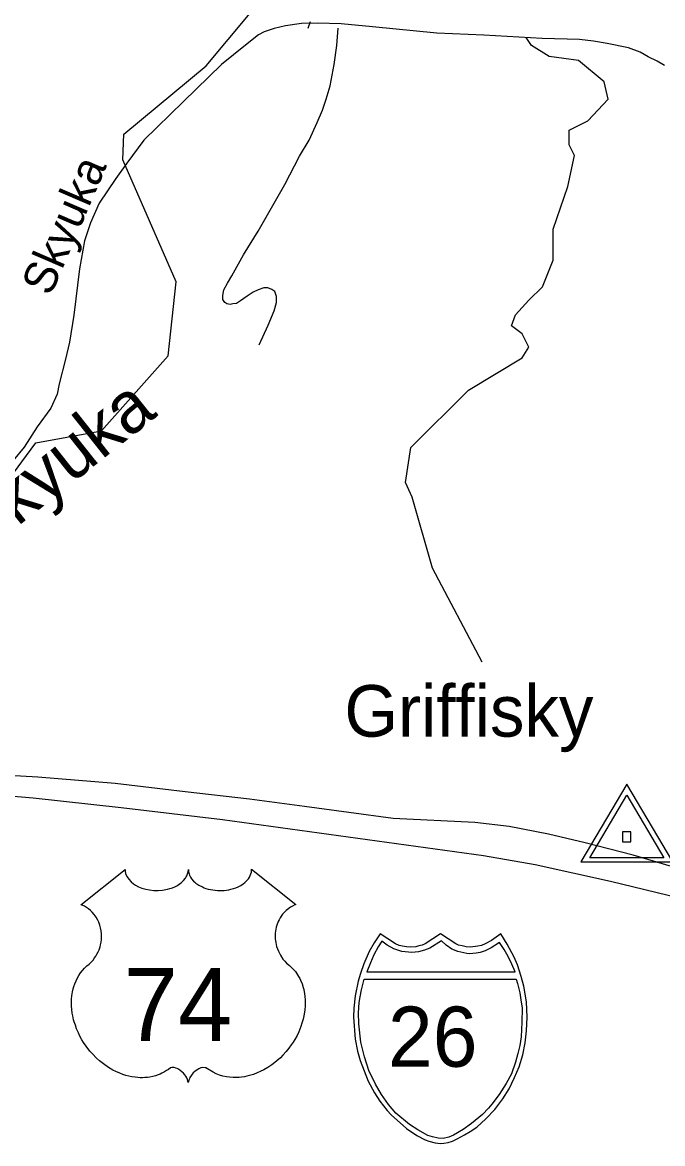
# Model space of a CAD drawing. Extents: x 990631 to 1056237, y 535999 to 585651.
# Drawn here: x 1037330 to 1039191, y 561980 to 565244 of the extents above; entities that cross this region are included whole.
import ezdxf

# ---------------------------------------------------------------- set-up
doc = ezdxf.new("R2010")
doc.units = 0
for name, color, linetype in [('Exist Hydrographic Creek Single Shore', 7, 'Continuous'), ('Exist Hydrographic Creek Single Shore Label', 7, 'Continuous'), ('Exist Road Non-System Type 51', 7, 'Continuous'), ('Exist Road Primary Interstate Divided Center Attributed', 7, 'Continuous'), ('Exist Road Primary Interstate Shield CELL', 7, 'Continuous'), ('Exist Road Primary Interstate Shield Number Label', 7, 'Continuous'), ('Exist Road Primary US Shield CELL', 7, 'Continuous'), ('Exist Road Primary US Shield Number Label', 7, 'Continuous'), ('Exist Road Secondary Type 51 Attributed', 7, 'Continuous'), ('Exist Road Secondary Type 51 Label', 7, 'Continuous'), ('Exist Survey Geodetic Marker CELL', 7, 'Continuous'), ('Exist Survey Geodetic Marker Label', 7, 'Continuous')]:
    doc.layers.add(name, color=color, linetype=linetype)

msp = doc.modelspace()

# ---------------------------------------------------------------- linework, layer by layer
at = {"layer": 'Exist Hydrographic Creek Single Shore'}
msp.add_lwpolyline([(1037044.6, 563559.5), (1037169.3, 563750.7), (1037368.1, 564019.8), (1037559.1, 564054.9), (1037753.3, 564272.7), (1037776.9, 564488.9), (1037621.7, 564843.2), (1037624, 564918.6), (1037863.8, 565117.3), (1038297.5, 565637), (1038320.6, 565836.7), (1038070.8, 566104.3), (1037992.3, 566256.9), (1037808.4, 567022), (1037738.6, 567180.9), (1037374.6, 567536.2), (1037272.5, 567731.9), (1037276.5, 567856.5), (1037246.9, 567972), (1036894.9, 568435.2)], dxfattribs=at)
at = {"layer": 'Exist Road Non-System Type 51'}
msp.add_line((1038166.4, 565245.3), (1038159.8, 565225.4), dxfattribs=at)
for points in [[(1038018.1, 564305.3), (1038044.1, 564362.6), (1038061.3, 564404.1), (1038068.2, 564428), (1038068.7, 564445.7), (1038063.2, 564460.1), (1038055.3, 564466.2), (1038043.4, 564470.7), (1038031.4, 564471.1), (1038015.3, 564465.6), (1038001, 564458.1), (1037982.7, 564446.7), (1037964.2, 564433.2), (1037951.9, 564425.5), (1037941.9, 564423.9), (1037933.8, 564422.3), (1037923.9, 564424.5), (1037917.9, 564428.6), (1037912.3, 564436.9), (1037912.7, 564448.9), (1037915.3, 564464.8), (1037925.9, 564484.4), (1037938.5, 564506), (1037972.5, 564566.9), (1038014.7, 564635.7), (1038057.3, 564710.5), (1038093.1, 564771.4), (1038135.8, 564854), (1038163.3, 564901.2), (1038187, 564952.4), (1038202.1, 564987.9), (1038213.1, 565019.7), (1038224.5, 565059.3), (1038236.4, 565121), (1038244.3, 565176.7), (1038247.9, 565226.6)], [(1038666.2, 563381.7), (1038522, 563654.7), (1038463.5, 563861.4), (1038444, 563904.3), (1038459.6, 564005.7), (1038627.2, 564173.5), (1038783.2, 564267.1), (1038802.7, 564298.3), (1038783.2, 564337.3), (1038752, 564360.7), (1038763.7, 564391.9), (1038802.7, 564434.8), (1038841.6, 564473.8), (1038872.8, 564551.8), (1038872.8, 564641.5), (1038915.7, 564766.3), (1038935.2, 564856), (1038919.6, 564887.2), (1038919.6, 564930.1), (1038974.2, 564957.4), (1039032.6, 565019.9), (1039021, 565070.6), (1038946.9, 565133), (1038861.1, 565144.7), (1038810.4, 565175.9), (1038810.4, 565175.9), (1038794.9, 565199.3)]]:
    msp.add_lwpolyline(points, dxfattribs=at)
at = {"layer": 'Exist Road Primary Interstate Divided Center Attributed'}
for points in [[(1039600.5, 562674), (1039581.5, 562681.8), (1039260.3, 562773.6), (1039105.6, 562819.5), (1038966.3, 562855.2), (1038859.2, 562880.8), (1038745.4, 562902.9), (1038645.1, 562914.8), (1038408, 562926.1), (1038149.5, 562961), (1037990.1, 562982.4), (1037802.6, 563003.9), (1037599, 563028), (1037373.9, 563046.7), (1037155.6, 563058.8), (1036983.1, 563069), (1036964, 563070.2), (1036848.9, 563077.1), (1036652.4, 563089.6)], [(1036616.9, 563035.1), (1037143.5, 563005.2), (1037360.5, 562986.4), (1037616.4, 562958.3), (1037911.1, 562923.5), (1038670.6, 562818.9), (1038820.6, 562792.1), (1039040.2, 562743.9), (1039239.7, 562694.9)]]:
    msp.add_lwpolyline(points, dxfattribs=at)
at = {"layer": 'Exist Road Primary Interstate Shield CELL'}
for points in [[(1038545.6, 561980), (1038555.1, 561980.9), (1038567.8, 561983.3), (1038580.2, 561987.4), (1038594.3, 561993.7), (1038615.2, 562005.2), (1038631.9, 562015), (1038651.3, 562028), (1038677.4, 562051.7), (1038703.4, 562079.1), (1038726.4, 562110.2), (1038744.7, 562139.2), (1038760.7, 562172.3), (1038774.2, 562203.3), (1038784.9, 562238.6), (1038791.9, 562272.8), (1038795.5, 562308.5), (1038797.9, 562348.1), (1038795.2, 562392.6), (1038787.4, 562438.2), (1038780.2, 562466.5), (1038769.1, 562500.5), (1038760.1, 562522.2), (1038739.3, 562560.6), (1038720.5, 562590.2), (1038693.3, 562571), (1038675.6, 562561.6), (1038664.7, 562556.7), (1038653.6, 562554.5), (1038633.1, 562552.1), (1038620.2, 562552.6), (1038608.2, 562555.3), (1038598.1, 562557.5), (1038589.9, 562561.6), (1038545.6, 562590.2), (1038501.3, 562561.6), (1038492.1, 562557.3), (1038482.6, 562555.3), (1038473.4, 562552.8), (1038458.3, 562552.1), (1038446.7, 562552.4), (1038434.8, 562554.5), (1038425.5, 562556.5), (1038414.9, 562561.6), (1038369.8, 562590.2), (1038352.1, 562564.5), (1038337.6, 562539.1), (1038322.3, 562503.1), (1038312.7, 562475.3), (1038305.9, 562452.4), (1038297.6, 562410.5), (1038293.3, 562373.9), (1038292.5, 562348.1), (1038297.2, 562283.6), (1038304.3, 562249.2), (1038311.5, 562221.4), (1038335.4, 562161.4), (1038353.3, 562127.8), (1038368.7, 562103.6), (1038390.3, 562076.4), (1038402, 562063.5), (1038446.8, 562024.3), (1038476.7, 562003.9), (1038500.6, 561991), (1038511.9, 561986.7), (1038529.5, 561981.8)], [(1038375.2, 562569.4), (1038364.2, 562552.5), (1038351.5, 562529.7), (1038341.4, 562506), (1038331, 562479.8), (1038762.6, 562479.7), (1038752.5, 562502.1), (1038741.8, 562524.6), (1038730.5, 562545.2), (1038716.8, 562565.1), (1038692.6, 562549.9), (1038675, 562541.5), (1038660.8, 562536.6), (1038648.8, 562533.9), (1038630.2, 562532.5), (1038621.9, 562533), (1038596, 562538.8), (1038578.4, 562546), (1038561.7, 562557.2), (1038548.2, 562569.9), (1038514, 562549.2), (1038498.9, 562542.5), (1038481.4, 562538.1), (1038462.3, 562535.7), (1038432.9, 562538.9), (1038409.8, 562546.8), (1038389.9, 562557.2)], [(1038765.1, 562458.4), (1038769.8, 562446.2), (1038776.1, 562419.2), (1038779.5, 562398.3), (1038782.9, 562374.3), (1038781.7, 562333.2), (1038779.7, 562290.6), (1038775.8, 562265.4), (1038770.6, 562242.5), (1038763.4, 562217), (1038751.9, 562183.2), (1038736, 562154.5), (1038716.1, 562122.7), (1038694.6, 562094.8), (1038685.3, 562083.3), (1038667.6, 562064.6), (1038635.3, 562038.7), (1038611.8, 562021.2), (1038583.7, 562004.5), (1038569.3, 561998.2), (1038552.7, 561994.7), (1038539, 561995.6), (1038522.3, 562000), (1038508.9, 562003.7), (1038479.5, 562019.6), (1038455.6, 562035.6), (1038415.8, 562068.2), (1038394.4, 562093.3), (1038374.3, 562122.7), (1038356.5, 562152.8), (1038337.4, 562192.5), (1038323.9, 562232.4), (1038314.1, 562275.4), (1038307.5, 562328.1), (1038306.8, 562360.1), (1038308.8, 562391), (1038311.7, 562407.1), (1038315.6, 562427.2), (1038323.5, 562458.2)]]:
    msp.add_lwpolyline(points, close=True, dxfattribs=at)
at = {"layer": 'Exist Road Primary US Shield CELL'}
msp.add_lwpolyline([(1037628.1, 562777.9), (1037628.4, 562772.5), (1037629.7, 562766.2), (1037630.7, 562763), (1037633.7, 562756.7), (1037638.5, 562749.4), (1037645.3, 562742.1), (1037653, 562735.8), (1037658.2, 562732.5), (1037666.9, 562727.8), (1037676.9, 562723.6), (1037688, 562720.4), (1037699.3, 562718.1), (1037711.7, 562716.8), (1037723.9, 562716.5), (1037737.1, 562717.5), (1037751.7, 562720.3), (1037758.5, 562722.1), (1037766, 562724.7), (1037773, 562727.5), (1037780.6, 562731.6), (1037786.8, 562735.6), (1037791.6, 562739.1), (1037798.4, 562745.6), (1037803.9, 562752.4), (1037806.1, 562756.2), (1037808.1, 562759.8), (1037810.8, 562767.6), (1037811.6, 562771), (1037812.1, 562778.1), (1037812.6, 562772.1), (1037813.2, 562768.4), (1037814.2, 562764.8), (1037815.7, 562760.9), (1037818.4, 562755.4), (1037821.5, 562750.9), (1037827.2, 562744.1), (1037830.8, 562740.8), (1037834, 562738.1), (1037842.8, 562732.1), (1037853, 562726.9), (1037858, 562724.7), (1037863.1, 562722.9), (1037869.7, 562720.9), (1037876.4, 562719.3), (1037883.1, 562718.2), (1037890, 562717.2), (1037896.9, 562716.7), (1037902.6, 562716.5), (1037909.6, 562716.6), (1037916.1, 562717), (1037922.7, 562717.7), (1037930, 562719), (1037935.8, 562720.2), (1037943.6, 562722.3), (1037950.6, 562724.8), (1037956.7, 562727.5), (1037964.7, 562731.6), (1037971.1, 562735.7), (1037975.9, 562739.5), (1037981.5, 562744.6), (1037986.8, 562750.8), (1037989.9, 562755.3), (1037992.1, 562759.9), (1037994.2, 562764.8), (1037995.4, 562769.9), (1037996, 562774.4), (1037996.1, 562778.3), (1038124.7, 562675.8), (1038121.7, 562674.7), (1038114.7, 562671.2), (1038109.2, 562668), (1038100.3, 562661.7), (1038096.5, 562658.3), (1038092.7, 562654.7), (1038089.2, 562650.9), (1038086.2, 562647.4), (1038082.4, 562642.2), (1038079.1, 562637), (1038075.8, 562631.3), (1038073.4, 562626.4), (1038069.5, 562616.1), (1038067.6, 562609.5), (1038066.4, 562604), (1038064.9, 562592.5), (1038064.5, 562587), (1038064.5, 562581.6), (1038064.8, 562575.9), (1038065.3, 562570.5), (1038066.3, 562564.8), (1038067.2, 562559.8), (1038068.8, 562553.6), (1038071.1, 562546.5), (1038073.9, 562539.6), (1038079.8, 562528.4), (1038087.3, 562517), (1038092.7, 562510.6), (1038098, 562505.1), (1038106, 562498.4), (1038110.3, 562494.6), (1038115.2, 562489.7), (1038123.3, 562480.4), (1038126.5, 562475.9), (1038129.8, 562471), (1038132.9, 562465.9), (1038135.9, 562460.4), (1038138.3, 562455.7), (1038142.9, 562444.6), (1038146.2, 562433.9), (1038147.7, 562428.3), (1038150.1, 562415.7), (1038151, 562409.5), (1038152, 562397.1), (1038152, 562382.3), (1038150.9, 562368.1), (1038148.2, 562351.6), (1038146, 562341.8), (1038142.6, 562330.3), (1038139.4, 562320.3), (1038133.5, 562305.7), (1038128.3, 562295), (1038121.5, 562282.6), (1038116.9, 562275), (1038111.5, 562267), (1038104.7, 562257.7), (1038096.8, 562247.8), (1038087.3, 562237.4), (1038079.7, 562229.8), (1038069.6, 562220.8), (1038063.6, 562215.8), (1038054.9, 562209.2), (1038043.1, 562201.3), (1038031.4, 562194.6), (1038021.4, 562189.5), (1038012.6, 562185.7), (1038001.2, 562181.3), (1037982.2, 562176.1), (1037975.3, 562174.7), (1037967.1, 562173.4), (1037959.5, 562172.7), (1037952, 562172.2), (1037942, 562172.2), (1037932, 562173), (1037922.6, 562174.4), (1037912.8, 562176.4), (1037902.6, 562179.4), (1037893.3, 562183.1), (1037883.8, 562187.7), (1037867.9, 562197.8), (1037863.3, 562200.2), (1037860.8, 562200.9), (1037854.6, 562201.2), (1037848.8, 562200), (1037842.9, 562197.6), (1037839.3, 562195.7), (1037834.6, 562192.6), (1037830.9, 562189.7), (1037826.5, 562185.5), (1037823.5, 562182), (1037821.2, 562179.3), (1037816.7, 562172.2), (1037815.1, 562168.9), (1037813.4, 562164.6), (1037812, 562158.2), (1037809.9, 562166.2), (1037807.6, 562171.5), (1037804.9, 562176.1), (1037802, 562180.1), (1037797.5, 562185.3), (1037793.5, 562189.2), (1037788.6, 562193.1), (1037783.5, 562196.2), (1037779.3, 562198.4), (1037775.5, 562199.8), (1037770.9, 562201), (1037767.1, 562201.3), (1037764, 562201.2), (1037759.7, 562200.2), (1037753.9, 562196), (1037748.4, 562192.2), (1037742.4, 562188.5), (1037735.3, 562184.7), (1037730, 562182.3), (1037723.8, 562179.8), (1037716.5, 562177.4), (1037708.6, 562175.3), (1037700.5, 562173.7), (1037693.3, 562172.6), (1037685.7, 562171.9), (1037678.7, 562171.7), (1037671.5, 562171.8), (1037664.8, 562172.3), (1037657, 562173), (1037647.2, 562174.4), (1037639.2, 562176.3), (1037630.7, 562178.5), (1037621.9, 562181.3), (1037612.6, 562184.8), (1037600.9, 562189.9), (1037592.8, 562194.1), (1037579.9, 562201.5), (1037564.9, 562211.9), (1037553.5, 562221.1), (1037545.2, 562228.6), (1037533, 562241.1), (1037525.8, 562249.2), (1037514.6, 562263.8), (1037507.3, 562274.4), (1037502.7, 562282.1), (1037495.8, 562294.6), (1037492.1, 562302.4), (1037487.2, 562313.8), (1037483.4, 562324.2), (1037480.2, 562334.1), (1037478.5, 562340.4), (1037476, 562351.4), (1037474.6, 562359.2), (1037473.1, 562369.9), (1037472.3, 562381.3), (1037472.2, 562391.7), (1037472.4, 562400.3), (1037473.4, 562410.4), (1037475.1, 562421.2), (1037477.2, 562430.4), (1037479, 562437), (1037481.8, 562445), (1037485.4, 562453.9), (1037489.6, 562462.4), (1037493.7, 562469.5), (1037498.8, 562477.1), (1037503.8, 562483.5), (1037510.4, 562490.7), (1037517.2, 562497.2), (1037523.5, 562502.3), (1037530.9, 562509.6), (1037534.8, 562514), (1037539.5, 562520.2), (1037543.2, 562525.9), (1037546.2, 562531), (1037550.1, 562538.5), (1037552.4, 562544.1), (1037555.4, 562552.8), (1037556.9, 562558.8), (1037558.4, 562566.7), (1037559.4, 562574), (1037559.7, 562583.2), (1037559.5, 562590.8), (1037558.5, 562599.7), (1037556.9, 562608.2), (1037554.8, 562615.7), (1037551.7, 562624.2), (1037548.7, 562630.4), (1037543.8, 562638.9), (1037538.3, 562646.7), (1037532.7, 562653.1), (1037527, 562658.8), (1037521.5, 562663), (1037516.3, 562666.7), (1037509.8, 562670.7), (1037503.5, 562673.8), (1037499.5, 562675.4)], close=True, dxfattribs=at)
at = {"layer": 'Exist Road Secondary Type 51 Attributed'}
msp.add_lwpolyline([(1039197, 565118.1), (1039175.3, 565130.8), (1039149.7, 565143.7), (1039126.3, 565157), (1039092, 565169.6), (1039030.2, 565182.2), (1038990.1, 565189.1), (1038950, 565193.7), (1038841.2, 565197.1), (1038671.8, 565206.3), (1038534.4, 565212), (1038347.7, 565230.4), (1038256.1, 565239.5), (1038187.4, 565241.8), (1038141.6, 565240.7), (1038094.7, 565233.8), (1038061.5, 565225.8), (1038032.9, 565216.6), (1038015.7, 565207.4), (1037977.9, 565177.6), (1037908.1, 565121.5), (1037798.1, 565013.8), (1037682.5, 564900.4), (1037633.3, 564833.9), (1037601.2, 564789.3), (1037553.1, 564717.1), (1037527.9, 564659.8), (1037509.6, 564608.2), (1037495.9, 564525.8), (1037478.7, 564391.7), (1037466.1, 564312.7), (1037454.7, 564263.4), (1037436.3, 564191.2), (1037430.6, 564161.4), (1037411.8, 564120.6), (1037372.1, 564066), (1037334.1, 564007.1), (1037302.9, 563968.2)], dxfattribs=at)
at = {"layer": 'Exist Survey Geodetic Marker CELL'}
for points in [[(1039221, 562800), (1039087, 563026.1), (1038953.6, 562800)], [(1039195.1, 562812.2), (1038979.5, 562812.2), (1039087, 562994.3)], [(1039099.3, 562858.7), (1039099.3, 562887), (1039075.1, 562887), (1039075.1, 562858.7)]]:
    msp.add_lwpolyline(points, close=True, dxfattribs=at)

# ---------------------------------------------------------------- texts
at = {"layer": 'Exist Hydrographic Creek Single Shore Label'}
msp.add_text('Skyuka', height=150, rotation=38.4062, dxfattribs=at).set_placement((1037209.9, 563691.9))
at = {"layer": 'Exist Road Primary Interstate Shield Number Label'}
msp.add_text('26', height=175, dxfattribs=at).set_placement((1038392.7, 562203.7))
at = {"layer": 'Exist Road Primary US Shield Number Label'}
msp.add_text('74', height=212.5, dxfattribs=at).set_placement((1037623.8, 562278.5))
at = {"layer": 'Exist Road Secondary Type 51 Label'}
msp.add_text('Skyuka', height=95, rotation=66.7285, dxfattribs=at).set_placement((1037411.1, 564444))
at = {"layer": 'Exist Survey Geodetic Marker Label'}
msp.add_text('Griffisky', height=150, dxfattribs=at).set_placement((1038265.9, 563164.5))

doc.saveas('drawing.dxf')
